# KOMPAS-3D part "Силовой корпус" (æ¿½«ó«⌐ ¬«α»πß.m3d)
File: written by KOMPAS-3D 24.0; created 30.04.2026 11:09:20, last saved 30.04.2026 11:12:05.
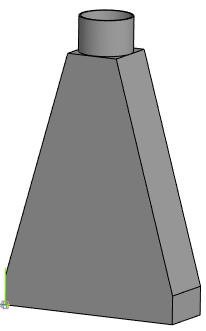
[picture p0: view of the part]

Document properties: Автор: USG_411; Полное имя файла: C:\Users\USG_411\Desktop\ИА-2904_411-12\Балка\Силовой корпус.m3d

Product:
- Part/product: Силовой корпус
    Масса: 5057.708614

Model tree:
1. Эскиз:1
2. Элемент выдавливания:1
     Расстояние 2 = 400
3. Эскиз:2  (with: Грань.Элемент выдавливания:1)
4. Элемент выдавливания:2
     Расстояние 1 = 250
